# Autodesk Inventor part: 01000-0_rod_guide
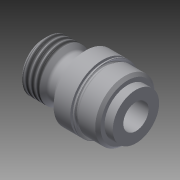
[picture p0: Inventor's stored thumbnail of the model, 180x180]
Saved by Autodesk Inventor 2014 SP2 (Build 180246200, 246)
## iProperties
Created: 2020-01
Part Number: 01000-0_rod_guide
Material: Generic
Catalog Web Link: www.cadenas.de
Description: Rod Guide-Original Line - Standard Air Cylinders
Vendor: BIMBA
Document SubType Name: Modeling
Designer: psadmin
Manufacturer: BIMBA
Mass: 1.13414 g
Surface Area: 11.0116 cm^2
Volume: 1.13414 cm^3
Density: 1 g/cm^3
Appearance: PSOLRGB-211-211-211
Category: PARTsolutions
Company: BIMBA
Title: 01000-0_rod_guide
Author: Cadenas PARTsolutions
Comments: Original Line - Standard Air Cylinders
PSOL_IDENT_0: {$CADENAS_DATA\23d-libs\bimba\bimba_brand\bimba_imperial\bimba_full_line\original_line_cylinders\sta
PSOL_IDENT_1: ndard_air_cylinders\rod_guide.prj},249 {VTYP=3D},{NB=01000-0_rod_guide},{LINA=01000-0_rod_guide},{NN=
PSOL_IDENT_2: Rod Guide},{DATE=23.12.2019 10:36:48},{GEOMDATE=15.10.2019 12:06:01},{VERSION=},{LINEID=20},{WBVAR=M
PSOL_IDENT_3: NT,ACTING,NR,K,Q,T1,T2,T3,T4,MB,TRIM,CUSH,RODTRANS},{WBNUMERIC=MB,TRIM,CUSH,RODTRANS}  {NB=01000-0_r
PSOL_IDENT_4: od_guide},{LINA=01000-0_rod_guide},{KT=DUMMY},{PN=01000},{BORE=0.43750000},{BOREPN=01},{MNT=},{MNTAL
PSOL_IDENT_5: G='' , 'Front Nose' , 'BF' , 'Front Block' , 'BFT' , 'Front Trunnion'},{ACTING=},{ACTINGALG= '' , 'S
PSOL_IDENT_6: ingle Acting' , 'R' , 'Reverse/Double Acting' },{NR=},{NRALG= '' , 'Without Non-rotating Rod' , 'NR'
PSOL_IDENT_7: , 'With Non-rotating Rod' },{K=},{Q=},{QALG= '' , 'Without Side Ported Rear Head' , 'Q' , 'With Sid
PSOL_IDENT_8: e Ported Rear Head' },{T1=},{T2=},{T3=},{T4=},{MB=0},{A1=0.6880},{A1N=0.6880},{A1P=1.1880},{A1B=1.18
PSOL_IDENT_9: 80},{A2=0.3130},{A2N=0.3130},{A2P=0.3750},{A3=0.1250},{A3N=0.1250},{A3P=0.6250},{A4=0.2500},{A4N=0.2
PSOL_IDENT_10: 500},{A4P=0.1880},{A5=0.0200},{A6=0.0620},{A6N=0.0620},{A6P=0.0000},{A7=0.1880},{A7N=0.1880},{A7P=0.
PSOL_IDENT_11: 5940},{A8=0.0200},{A8N=0.0200},{A8NR=0.0200},{D1=0.4840},{D1N=0.4840},{D1P=0.7380},{D1B=0.0000},{D2=
PSOL_IDENT_12: 0.4465},{D3=0.3470},{D3N=0.3470},{D3P=0.0000},{D4=0.2220},{D4N=0.2220},{D4P=0.2820},{D4NR=0.2820},{D
PSOL_IDENT_13: 5=0.1895},{D5N=0.1895},{D5NR=0.1895},{C1=0.000},{C2=0.0200},{C2N=0.0200},{C2P=0.0200},{C3=0.0000},{C
PSOL_IDENT_14: 3N=0.0000},{C3P=0.0000},{C4=0.0000},{C4N=0.0000},{C4P=0.0000},{NDM=0.3750},{NDMN=0.3750},{NDMP=0.437
PSOL_IDENT_15: 5},{TAB=UNF},{D6=0.3725},{D6N=0.3725},{D6P=0.4350},{A9=0.0500},{A9N=0.0500},{A9P=0.0475},{D7=0.3100}
PSOL_IDENT_16: ,{D7N=0.3100},{D7P=0.3600},{A10=0.0655},{A10N=0.0655},{A10P=0.0775},{R1=0.0265},{R1N=0.0265},{R1P=0.
PSOL_IDENT_17: 0315},{D8=0.0000},{D9=0.0000},{D10=0.0000},{A11=0.0000},{A12=0.0000},{A13=0.0000},{A14=0.4680},{A14N=
PSOL_IDENT_18: 0.4680},{A14B=0.4690},{D11=0.0000},{D11N=0.0000},{NDM2=0.1900},{NDM2N=0.1900},{NDM2DP=0.0000},{THREA
PSOL_IDENT_19: D=0},{HEX=0.1920},{HEXN=0.1920},{S1=0.7500},{B1=0.1275},{B2=0.3120},{B22=0.4380},{DB=0.3020},{B3=0.2
PSOL_IDENT_20: 200},{B4=0.4380},{X1=0.0620},{X2=0.4345},{NDM3=0.1640},{NDM4=0.1640},{NDM4DP=0.2500},{DD=0.7500},{CB=
PSOL_IDENT_21: 0.0000},{CBDP=0.0000},{PORT=1},{XT=0.3120},{XTX=0.3120},{XT1=0.3740},{XT2=0.2500},{NDMH=0.0000},{OD=
PSOL_IDENT_22: 0.4840},{ID=0.4465},{G=0.0000},{PNUT=0.2630},{TRIM=0},{C11=0.0000},{C22=0.0000},{C33=0.0000},{C44=0.
PSOL_IDENT_23: 0000},{C55=0.0000},{CD1=0.0000},{CD2=0.0000},{CD3=0.0000},{CNDM3=0.0000},{CTAB3=0.0000},{CUSH=0},{XX=
PSOL_IDENT_24: 0.43800},{LCD=0.0000},{RODTRANS=0.00000}
NN: Rod Guide
NT: Original Line - Standard Air Cylinders
NB: 01000-0_rod_guide
NBSYN: $PN.-$RODTRANS._rod_guide
LINA: 01000-0_rod_guide
BORE: 0
BOREPN: 01
MNT: Front Nose
MNTALG: '' , 'Front Nose' , 'BF' , 'Front Block' , 'BFT' , 'Front Trunnion'
ACTING: Single Acting
NR: Without Non-rotating Rod
K: Standard
Q: Without Side Ported Rear Head
T1: without T1
T2: without T2
T3: without T3
T4: without T4
MB: 0
A1N: 0.688
A1P: 1.188
A1B: 1.188
A2N: 0.313
A2P: 0.375
A3N: 0.125
A3P: 0.625
A4N: 0.25
A4P: 0.188
A5: 0.02
A6N: 0.062
A6P: 0
A7N: 0.188
A7P: 0.594
A8N: 0.02
A8NR: 0.02
D1N: 0.484
D1P: 0.738
D1B: 0
D2: 0.4465
D3N: 0.347
D3P: 0
D4N: 0.222
D4P: 0.282
D4NR: 0.282
D5N: 0.1895
D5NR: 0.1895
C1: 0
C2N: 0.02
C2P: 0.02
C3N: 0
C3P: 0
C4N: 0
C4P: 0
NDMN: 0.375
NDMP: 0.4375
TAB: UNF
D6N: 0.3725
D6P: 0.435
A9N: 0.05
A9P: 0.0475
D7N: 0.31
D7P: 0.36
A10N: 0.0655
A10P: 0.0775
R1N: 0.0265
R1P: 0.0315
D8: 0
D9: 0
D10: 0
A11: 0
A12: 0
A13: 0
A14N: 0.468
A14B: 0.469
D11N: 0
NDM2N: 0.19
NDM2DP: 0
HEXN: 0.192
S1: 0.75
B1: 0.1275
B2: 0.312
B22: 0.438
DB: 0.302
B3: 0.22
B4: 0.438
X1: 0.062
X2: 0.4345
NDM3: 0.164
NDM4: 0.164
NDM4DP: 0.25
DD: 0.75
CB: 0
CBDP: 0
XTX: 0.312
XT1: 0.374
XT2: 0.25
NDMH: 0
TRIM: 0
C11: 0
C22: 0
C33: 0
C44: 0
C55: 0
CD1: 0
CD2: 0
CD3: 0
CNDM3: 0
CTAB3: 0.0000
CUSH: 0
LCD: 0
RODTRANS: 0
SUPPLIER: BIMBA
ARTICLENO: 01000-0_rod_guide
BOMINFO: 01000-0_rod_guide
CREATOR: CADENAS GmbH
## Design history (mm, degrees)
sketch "Sketch_2"
  geometry: L1 (7.95, 0)-(0, 0); L2 (0, 0)-(0, 4.133); L3 (0, 4.133)-(0.63, 4.763); L4 (0.63, 4.763)-(3.911, 4.763); L5 (3.911, 4.763)-(4.541, 4.134); L6 (5.017, 3.937)-(6.007, 3.937); L7 (6.68, 4.61)-(6.68, 4.731); L8 (6.68, 4.731)-(7.95, 4.731); L9 (7.95, 4.731)-(7.95, 0); L10 (7.95, 0)-(0, 0); A1 r 0.673 centre (5.017, 4.61) between (4.541, 4.134) and (5.017, 3.937); A2 r 0.673 centre (6.007, 4.61) between (6.007, 3.937) and (6.68, 4.61)
  constraints: 20 end point, 4 point on circle, 2 centre point
revolve "Revolution1" sketch "Sketch_2" stored, may be unused: angle "d0" = 360 deg
thread "Thread1" dims "d1" = 3.28071, "d2" = 0
sketch "Sketch_3"
  geometry: L1 (15.9, 0)-(7.95, 0); L2 (7.95, 0)-(7.95, 6.147); L3 (7.95, 6.147)-(11.125, 6.147); L4 (11.125, 6.147)-(11.125, 5.163); L5 (11.125, 5.163)-(11.633, 5.163); L6 (11.633, 5.163)-(12.141, 5.671); L7 (12.141, 5.671)-(15.392, 5.671); L8 (15.392, 5.671)-(15.9, 5.163); L9 (15.9, 5.163)-(15.9, 0); L10 (15.9, 0)-(7.95, 0)
  constraints: 20 end point
revolve "Revolution2" sketch "Sketch_3" stored, may be unused: angle "d3" = 360 deg
sketch "Sketch_4"
  geometry: L1 (17.475, 0)-(15.9, 0); L2 (15.9, 0)-(15.9, 4.407); L3 (15.9, 4.407)-(17.475, 4.407); L4 (17.475, 4.407)-(17.475, 0); L5 (17.475, 0)-(15.9, 0)
  constraints: 10 end point
revolve "Revolution3" sketch "Sketch_4" stored, may be unused: angle "d4" = 360 deg
sketch "Sketch4"
  geometry: 1 further point
hole "Hole1" sketch "Sketch4" at (0, 0) diameter "d5" = 4.8133; stored, may be unused: countersink angle "d9" = 90 deg, drill point angle "d11" = 0 deg; dims "d6" = 19.05, "d7" = 5.8293, "d8" = 6.35, "d10" = 17.4752
sketch "Sketch_47"
  geometry: L1 (11.633, 0)-(11.125, 0); L2 (11.125, 5.66)-(11.125, 4.909); L3 (11.125, 4.909)-(11.633, 4.909); L4 (11.633, 4.909)-(11.633, 5.163); L5 (11.633, 5.163)-(11.379, 5.163); L6 (11.379, 5.163)-(11.237, 5.305); L7 (11.237, 5.485)-(11.815, 6.063); L8 (11.815, 6.063)-(11.815, 6.147); L9 (11.815, 6.147)-(11.612, 6.147); L10 (11.612, 6.147)-(11.125, 5.66); A1 r 0.127 centre (11.327, 5.395) between (11.237, 5.485) and (11.237, 5.305)
  constraints: 20 end point, 2 point on circle, 1 centre point
revolve "Revolution4" sketch "Sketch_47" stored, may be unused: angle "d12" = 360 deg
node "dp1_XY"
node "dp1_YZ"
node "dp1_ZX"
node "dp1_X"
node "dp1_Y"
node "dp1_Z"
node "dp1_Center"
node "dp2_XY"
node "dp2_YZ"
node "dp2_ZX"
node "dp2_X"
node "dp2_Y"
node "dp2_Z"
node "dp2_Center"
node "hh_XY"
node "hh_YZ"
node "hh_ZX"
node "hh_X"
node "hh_Y"
node "hh_Z"
node "hh_Center"
node "rod_guide_XY"
node "rod_guide_YZ"
node "rod_guide_ZX"
node "rod_guide_X"
node "rod_guide_Y"
node "rod_guide_Z"
node "rod_guide_Center"
node "s1_XY"
node "s1_YZ"
node "s1_ZX"
node "s1_X"
node "s1_Y"
node "s1_Z"
node "s1_Center"
node "s2_XY"
node "s2_YZ"
node "s2_ZX"
node "s2_X"
node "s2_Y"
node "s2_Z"
node "s2_Center"
node "t1_XY"
node "t1_YZ"
node "t1_ZX"
node "t1_X"
node "t1_Y"
node "t1_Z"
node "t1_Center"
node "t111_XY"
node "t111_YZ"
node "t111_ZX"
node "t111_X"
node "t111_Y"
node "t111_Z"
node "t111_Center"
node "to_foot_bracket_XY"
node "to_foot_bracket_YZ"
node "to_foot_bracket_ZX"
node "to_foot_bracket_X"
node "to_foot_bracket_Y"
node "to_foot_bracket_Z"
node "to_foot_bracket_Center"
node "to_nut_XY"
node "to_nut_YZ"
node "to_nut_ZX"
node "to_nut_X"
node "to_nut_Y"
node "to_nut_Z"
node "to_nut_Center"
node "to_rod_XY"
node "to_rod_YZ"
node "to_rod_ZX"
node "to_rod_X"
node "to_rod_Y"
node "to_rod_Z"
node "to_rod_Center"
node "to_screw_XY"
node "to_screw_YZ"
node "to_screw_ZX"
node "to_screw_X"
node "to_screw_Y"
node "to_screw_Z"
node "to_screw_Center"
node "to_trunnion_brackets_XY"
node "to_trunnion_brackets_YZ"
node "to_trunnion_brackets_ZX"
node "to_trunnion_brackets_X"
node "to_trunnion_brackets_Y"
node "to_trunnion_brackets_Z"
node "to_trunnion_brackets_Center"
node "to_trunnion_brackets1_XY"
node "to_trunnion_brackets1_YZ"
node "to_trunnion_brackets1_ZX"
node "to_trunnion_brackets1_X"
node "to_trunnion_brackets1_Y"
node "to_trunnion_brackets1_Z"
node "to_trunnion_brackets1_Center"
node "to_trunnion_brackets2_XY"
node "to_trunnion_brackets2_YZ"
node "to_trunnion_brackets2_ZX"
node "to_trunnion_brackets2_X"
node "to_trunnion_brackets2_Y"
node "to_trunnion_brackets2_Z"
node "to_trunnion_brackets2_Center"
node "to_tube_XY"
node "to_tube_YZ"
node "to_tube_ZX"
node "to_tube_X"
node "to_tube_Y"
node "to_tube_Z"
node "to_tube_Center"
body "Solid1"
other parameters: "d13" = 0, "d14" = 0, "d15" = 0, "d16" = 0, "d17" = 0, "d18" = 0
